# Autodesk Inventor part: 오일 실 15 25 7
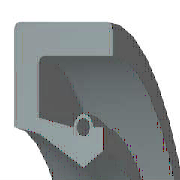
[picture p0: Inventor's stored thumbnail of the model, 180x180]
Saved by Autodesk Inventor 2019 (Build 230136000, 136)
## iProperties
Created: 2012-02
Part Number: 오일 실 15 25 7
Material: 고무
Description: 오일-실
Document SubType Name: Modeling
Standard: KS B 2804
Designer: mduedu
Standards Organization: KS
Language: ko-KR
Size Designation: S - 15 25 7
Categories: <MemberInstance><Categories><Category DisplayName="샤프트 부품" InternalName="7f7aeb1f-a693-4053-b835-cee3144e0d98" Mnemonic="SHFT"><Category DisplayName="실링" Intern
Density: 0.93 g/cm^3
Appearance: 고무 - 검은색 - 버전 1.1
IsCustomPart: 1
Author: mduedu
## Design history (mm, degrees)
revolve "본체" stored, may be unused: angle "d17" = 90 deg
revolve "스프링1" stored, may be unused: angle "d18" = 90 deg
body "Solid1"
sketch "스케치1"
  geometry: L1 (0, 12.5)-(7, 12.5); L2 (7, 12.5)-(7, 11.25); L3 (7, 11.25)-(1.75, 11.25); L4 (0, 12.5)-(0, 9.6); L5 (0, 9.6)-(1.75, 9.25); L6 (1.75, 9.25)-(4.9, 7.5); L7 (4.9, 7.5)-(0, 7.5); L8 (6.3, 8.375)-(6.3, 9.6); L9 (0, 0)-(9.586, 0) reference; L10 (4.9, 7.5)-(6.3, 8.375); L11 (0, 18)-(0, -3) reference; L12 (-1.917, 0)-(11.503, 0) reference; L13 (4.2, 9.6)-(1.75, 10.09); L14 (1.75, 10.09)-(1.75, 11.25); L15 (6.3, 9.6)-(5.6, 9.6); C1 r 0.455 at (4.9, 9.6); A1 r 0.7 centre (4.9, 9.6) between (5.6, 9.6) and (4.2, 9.6)
  constraints: 26 end point, 5 horizontal alignment, 4 perpendicular, 2 centre point, 2 collinear, 2 horizontal, 2 parallel, 2 point on circle, 2 point on line, 2 vertical alignment, 1 coincident
  dimensions: "d0" = 25 diameter of L1 L9 (= SD2); "d1" = 16.75 diameter of L8.start L9 (= ABDM); "d2" = 1.25 distance of L1.end L2.end (computed from SD); "d3" = 0.91 diameter of C1 (= SPDI); "d4" = 1.4 diameter of A1 (= SPDA); "d5" = 15 diameter of L6.end L9 (= NND); "d6" = 18.5 diameter of L5.end L9 (= TKDM); "d7" = 19.2 diameter of L4.end L9 (= HLDM); "d8" = 4.9 distance from line of C1.centre L4 (= SPDST); "d9" = 6.3 distance between parallel lines of L8 L4 (= SDI); "d10" = 7 distance between parallel lines of L2 L4 (= SWDT); "d12" = 1.75 distance between parallel lines of L14 L4 (= SD)
fillet "모깎기1" dims "d11" = 0.3 (= RR)
other parameters: "SD2" = 25 [user parameter; used in 1 equation term], "SWDT" = 7 [user parameter; used in 1 equation term], "RR" = 0.3 [user parameter; used in 1 equation term], "SD" = 1.75 [user parameter; used in 2 equation terms], "NND" = 15 [user parameter; used in 1 equation term], "SPDA" = 1.4 [user parameter; used in 1 equation term], "SPDI" = 0.91 [user parameter; used in 1 equation term], "TKDM" = 18.5 [user parameter; used in 1 equation term], "HLDM" = 19.2 [user parameter; used in 1 equation term], "ABDM" = 16.75 [user parameter; used in 1 equation term], "SDI" = 6.3 [user parameter; used in 1 equation term], "SPDST" = 4.9 [user parameter; used in 1 equation term], "d13" = 0, "d14" = 0, "d15" = 0, "LAB" = 0.35 [user parameter]
